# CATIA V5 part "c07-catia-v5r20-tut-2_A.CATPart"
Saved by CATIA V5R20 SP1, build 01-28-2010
Part number: Part1
Bounding box of the stored display mesh (mm): x 0 to 32, y -32 to 32, z -9 to 36
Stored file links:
  D:\v5_r20\psrt_files_downloaded\c07-catia-v5r20-prt\c07-catia-v5r20-tut-2_A.CATPart
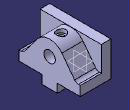
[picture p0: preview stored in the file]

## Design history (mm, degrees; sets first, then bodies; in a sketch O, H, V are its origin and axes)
Body1 (main body)
  Sketch1 on zx-plane, origin (0, 0, 0), H (-1, 0, 0), V (0, 0, 1)
    point P1 (-32, 0)
    line L1 (-32, 0) -> (0, 0)
    line L2 (0, 0) -> (0, 36)
    line L3 (0, 36) -> (-10, 36)
    line L4 (-10, 36) -> (-10, 10)
    line L5 (-10, 10) -> (-32, 10)
    line L6 (-32, 10) -> (-32, 0)
    length L2 = 36
    length L3 = 10
    length L6 = 10
    length L1 = 32
    coincidence: P1 H
    horizontal: L1 H, L3 H, L5 H
    vertical: L2 V, L4 V, L6 V
  Pad1: profile Sketch1, direction (0, 1, 0), length 32, mirrored extent
  Sketch2 on face of Pad1, origin (32, 0, 0), H (0, 1, 0), V (0, 0, 1)
    point P1 (-27.5, 10)
    line L1 (-27.5, 10) -> (-12.8, 29.6)
    arc A1 centre (0, 20) radius 16 from (-12.8, 29.6) to (12.8, 29.6) cw
    point P3 (0, 20)
    line L2 (12.8, 29.6) -> (27.5, 10)
    point P5 (27.5, 10)
    line L3 (27.5, 10) -> (-27.5, 10)
    reference projected line E1 (-32, 10) -> (32, 10) from edge [face of Pad1 | face of Pad1]
    reference projected line E2 (-32, 36) -> (32, 36) from edge [face of Pad1 | face of Pad1]
    length L3 = 55
    radius A1 = 16
    tangency: A1 L1, L2 A1, A1 E2
    horizontal: L3 H
    coincidence: L3 E1, P3 V
    symmetry: P5 P1 V
  Pad2: profile Sketch2, direction (-1, 0, 0), up to the existing solid (limit type 2)
  Sketch3 on face of Pad1, origin (32, 0, 0), H (0, 1, 0), V (0, 0, 1)
    point P1 (-8, 0)
    line L1 (-8, 0) -> (8, 0)
    line L2 (8, 0) -> (8, -9)
    line L3 (8, -9) -> (-8, -9)
    line L4 (-8, -9) -> (-8, 0)
    length L2 = 9
    length L3 = 16
    coincidence: P1 H
    horizontal: L1 H, L3 H
    vertical: L2 V, L4 V
    midpoint: O L1
  Pad3: profile Sketch3, direction (-1, 0, 0), length 32
  Sketch4 on face of Pad1, origin (32, 1.3275, 27.1999), H (0, 1, 0), V (0, 0, 1)
    point P1 (-1.3275, -7.1999)
    reference projected arc E1 centre (-1.3275, -7.1999) radius 16 from (11.4725, 2.4001) to (-14.1275, 2.4001) ccw from edge [face of Pad2 | face of Pad2]
    concentricity: P1 E1
  Hole1: placed by Sketch4, at (32, 0, 20) direction (-1, 0, 0), diameter 12, depth 24
  Sketch5, origin (20, 0, 36), H (1, 0, 0), V (0, 1, 0)
    point P1 (0, 0)
    reference projected point E1 (0, 0) from vertex of Sketch8
    coincidence: E1 P1
  Hole2: placed by Sketch5, at (20, 0, 36) direction (0, 0, -1), diameter 6, depth 16, counterbore diameter 10, counterbore depth 4
  Fillet1: radius 5, on edge [face of Pad1 | face of Pad2]; edge [face of Pad2 | face of Pad1]
  Sketch6 on face of Pad3, origin (17.7485, -3.919, -9), H (1, 0, 0), V (0, -1, 0)
    point P1 (6.2515, -3.919)
    reference projected line E1 (14.2515, 4.081) -> (14.2515, -11.919) from edge [face of Pad3 | face of Pad3]
    reference projected line E2 (14.2515, -35.919) -> (-17.7485, -35.919) from edge [face of Pad1 | face of Pad1]
    distance P1 E1 = 8
    distance E2 P1 = 32
  Hole3: placed by Sketch6, at (24, 0, -9) direction (0, 0, 1), diameter 6, depth 16, V-bottom angle 120
  Sketch7 on face of Pad3, origin (11.2705, -0.1534, -9), H (1, 0, 0), V (0, -1, 0)
    point P1 (-3.2705, -0.1534)
    reference projected line E1 (20.7295, -32.1534) -> (-11.2705, -32.1534) from edge [face of Pad1 | face of Pad1]
    reference projected line E2 (-11.2705, 7.8466) -> (-11.2705, -8.1534) from edge [face of Pad3 | face of Pad3]
    distance P1 E1 = 32
    distance P1 E2 = 8
  Hole4: placed by Sketch7, at (8, 0, -9) direction (0, 0, 1), diameter 6, depth 16, V-bottom angle 120
  Sketch8 on zx-plane, origin (0, 0, 0), H (-1, 0, 0), V (0, 0, 1)
    point P1 (-20, 36)
    reference projected line E1 (0, 36) -> (-10, 36) from edge [face of Pad1 | face of Pad1]
    reference projected line E2 (0, 0) -> (0, 36) from edge [face of Pad1 | face of Pad1]
    distance E2 P1 = 20
    coincidence: P1 E1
